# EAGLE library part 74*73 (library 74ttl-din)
Dual J-K FLIP FLOP, clear
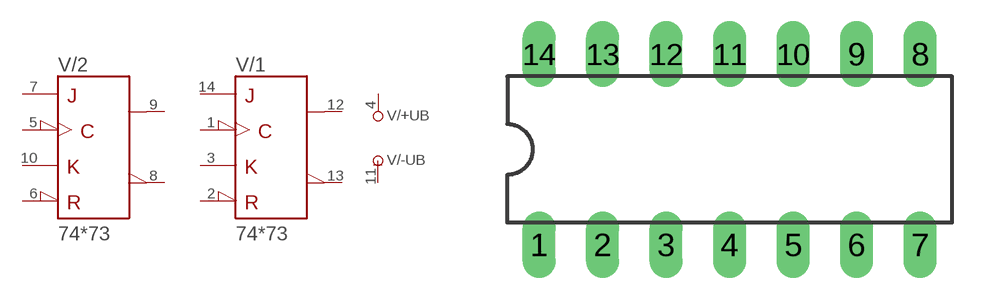
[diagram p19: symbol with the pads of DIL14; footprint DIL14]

Designator prefix V; gates /+UB=+UB /-UB=-UB /1=73 /2=73

## 7473N  [DIL14]
1  /1:CLK  in
2  /1:CLR\  in
3  /1:K  in
4  /+UB:+UB  pwr
5  /2:CLK  in
6  /2:CLR\  in
7  /2:J  in
8  /2:Q\  out
9  /2:Q  out
10  /2:K  in
11  /-UB:-UB  pwr
12  /1:Q  out
13  /1:Q\  out
14  /1:J  in

## Footprint DIL14 (pad centres in mm)
Dual In Line Package
drill 0.813 long: 1 -7.62,-3.81; 2 -5.08,-3.81; 3 -2.54,-3.81; 4 0,-3.81; 5 2.54,-3.81; 6 5.08,-3.81; 7 7.62,-3.81; 8 7.62,3.81; 9 5.08,3.81; 10 2.54,3.81; 11 0,3.81; 12 -2.54,3.81; 13 -5.08,3.81; 14 -7.62,3.81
